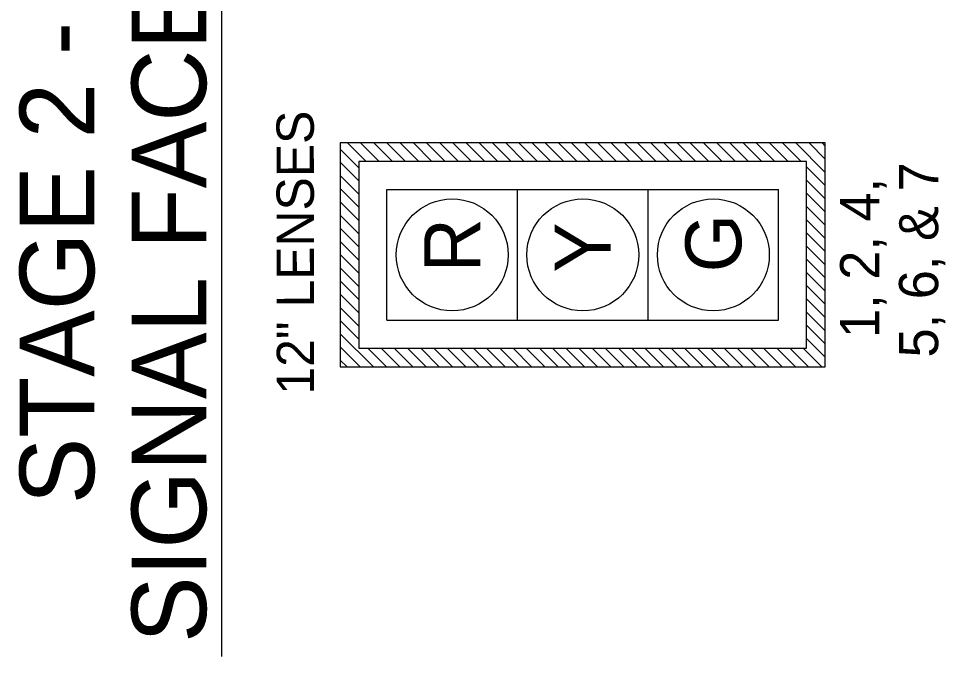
# Model space of a CAD drawing. Extents: x 610547 to 611161, y 419122 to 420064.
# Drawn here: x 610546.6 to 610646, y 419292 to 419360.3 of the extents above; entities that cross this region are included whole.
import ezdxf

# ---------------------------------------------------------------- set-up
doc = ezdxf.new("R2010")
doc.units = 0
for name, color, linetype in [('C-ANNO-TEXT', 7, 'Continuous'), ('Level 57', 7, 'Continuous'), ('Level 61', 7, 'Continuous'), ('T_Drafting', 7, 'Continuous')]:
    doc.layers.add(name, color=color, linetype=linetype)

msp = doc.modelspace()

# ---------------------------------------------------------------- linework, layer by layer
at = {"layer": 'Level 57'}
msp.add_line((610568.436, 419291.951), (610568.436, 419376.152), dxfattribs=at)
at = {"layer": 'T_Drafting'}
for p, q in [((610633.13, 419347.005), (610581.13, 419347.005)), ((610581.13, 419347.005), (610581.13, 419323.005)), ((610583.13, 419344.35), (610581.13, 419346.35)), ((610583.89, 419345.005), (610581.89, 419347.005)), ((610585.305, 419345.005), (610583.305, 419347.005)), ((610586.719, 419345.005), (610584.719, 419347.005)), ((610588.133, 419345.005), (610586.133, 419347.005)), ((610589.547, 419345.005), (610587.547, 419347.005)), ((610590.961, 419345.005), (610588.961, 419347.005)), ((610592.376, 419345.005), (610590.376, 419347.005)), ((610593.79, 419345.005), (610591.79, 419347.005)), ((610595.204, 419345.005), (610593.204, 419347.005)), ((610596.618, 419345.005), (610594.618, 419347.005)), ((610598.032, 419345.005), (610596.032, 419347.005)), ((610599.447, 419345.005), (610597.447, 419347.005)), ((610600.861, 419345.005), (610598.861, 419347.005)), ((610602.275, 419345.005), (610600.275, 419347.005)), ((610603.689, 419345.005), (610601.689, 419347.005)), ((610605.104, 419345.005), (610603.104, 419347.005)), ((610606.518, 419345.005), (610604.518, 419347.005)), ((610607.932, 419345.005), (610605.932, 419347.005)), ((610609.346, 419345.005), (610607.346, 419347.005)), ((610610.76, 419345.005), (610608.76, 419347.005)), ((610612.175, 419345.005), (610610.175, 419347.005)), ((610613.589, 419345.005), (610611.589, 419347.005)), ((610615.003, 419345.005), (610613.003, 419347.005)), ((610616.417, 419345.005), (610614.417, 419347.005)), ((610617.831, 419345.005), (610615.831, 419347.005)), ((610619.246, 419345.005), (610617.246, 419347.005)), ((610620.66, 419345.005), (610618.66, 419347.005)), ((610622.074, 419345.005), (610620.074, 419347.005)), ((610623.488, 419345.005), (610621.488, 419347.005)), ((610624.903, 419345.005), (610622.903, 419347.005)), ((610626.317, 419345.005), (610624.317, 419347.005)), ((610627.731, 419345.005), (610625.731, 419347.005)), ((610629.145, 419345.005), (610627.145, 419347.005)), ((610630.559, 419345.005), (610628.559, 419347.005)), ((610633.13, 419343.848), (610629.974, 419347.005)), ((610633.13, 419345.262), (610631.388, 419347.005)), ((610633.13, 419346.676), (610632.802, 419347.005)), ((610633.13, 419323.005), (610633.13, 419347.005)), ((610583.13, 419342.936), (610581.13, 419344.936)), ((610633.13, 419342.434), (610631.13, 419344.434)), ((610583.13, 419341.522), (610581.13, 419343.522)), ((610583.13, 419340.108), (610581.13, 419342.108)), ((610633.13, 419341.019), (610631.13, 419343.019)), ((610586.13, 419328.005), (610586.13, 419342.005)), ((610586.13, 419342.005), (610600.13, 419342.005)), ((610600.13, 419328.005), (610600.13, 419342.005)), ((610600.13, 419342.005), (610614.13, 419342.005)), ((610614.13, 419328.005), (610614.13, 419342.005)), ((610614.13, 419342.005), (610628.13, 419342.005)), ((610628.13, 419328.005), (610628.13, 419342.005)), ((610633.13, 419339.605), (610631.13, 419341.605)), ((610583.13, 419338.694), (610581.13, 419340.694)), ((610633.13, 419338.191), (610631.13, 419340.191)), ((610583.13, 419337.279), (610581.13, 419339.279)), ((610633.13, 419336.777), (610631.13, 419338.777)), ((610583.13, 419335.865), (610581.13, 419337.865)), ((610633.13, 419335.363), (610631.13, 419337.363)), ((610583.13, 419334.451), (610581.13, 419336.451)), ((610633.13, 419333.948), (610631.13, 419335.948)), ((610583.13, 419333.037), (610581.13, 419335.037)), ((610633.13, 419332.534), (610631.13, 419334.534)), ((610583.13, 419331.622), (610581.13, 419333.622)), ((610633.13, 419331.12), (610631.13, 419333.12)), ((610583.13, 419330.208), (610581.13, 419332.208)), ((610633.13, 419329.706), (610631.13, 419331.706)), ((610583.13, 419328.794), (610581.13, 419330.794)), ((610633.13, 419328.291), (610631.13, 419330.291)), ((610583.13, 419327.38), (610581.13, 419329.38)), ((610633.13, 419326.877), (610631.13, 419328.877)), ((610583.13, 419325.966), (610581.13, 419327.966)), ((610586.13, 419328.005), (610600.13, 419328.005)), ((610600.13, 419328.005), (610614.13, 419328.005)), ((610614.13, 419328.005), (610628.13, 419328.005)), ((610633.13, 419325.463), (610631.13, 419327.463)), ((610584.677, 419323.005), (610581.13, 419326.551)), ((610633.13, 419324.049), (610631.13, 419326.049)), ((610583.263, 419323.005), (610581.13, 419325.137)), ((610586.091, 419323.005), (610584.091, 419325.005)), ((610587.506, 419323.005), (610585.506, 419325.005)), ((610588.92, 419323.005), (610586.92, 419325.005)), ((610590.334, 419323.005), (610588.334, 419325.005)), ((610591.748, 419323.005), (610589.748, 419325.005)), ((610593.162, 419323.005), (610591.162, 419325.005)), ((610594.577, 419323.005), (610592.577, 419325.005)), ((610595.991, 419323.005), (610593.991, 419325.005)), ((610597.405, 419323.005), (610595.405, 419325.005)), ((610598.819, 419323.005), (610596.819, 419325.005)), ((610600.234, 419323.005), (610598.234, 419325.005)), ((610601.648, 419323.005), (610599.648, 419325.005)), ((610603.062, 419323.005), (610601.062, 419325.005)), ((610604.476, 419323.005), (610602.476, 419325.005)), ((610605.89, 419323.005), (610603.89, 419325.005)), ((610607.305, 419323.005), (610605.305, 419325.005)), ((610608.719, 419323.005), (610606.719, 419325.005)), ((610610.133, 419323.005), (610608.133, 419325.005)), ((610611.547, 419323.005), (610609.547, 419325.005)), ((610612.961, 419323.005), (610610.961, 419325.005)), ((610614.376, 419323.005), (610612.376, 419325.005)), ((610615.79, 419323.005), (610613.79, 419325.005)), ((610617.204, 419323.005), (610615.204, 419325.005)), ((610618.618, 419323.005), (610616.618, 419325.005)), ((610620.032, 419323.005), (610618.032, 419325.005)), ((610621.447, 419323.005), (610619.447, 419325.005)), ((610622.861, 419323.005), (610620.861, 419325.005)), ((610624.275, 419323.005), (610622.275, 419325.005)), ((610625.689, 419323.005), (610623.689, 419325.005)), ((610627.104, 419323.005), (610625.104, 419325.005)), ((610628.518, 419323.005), (610626.518, 419325.005)), ((610629.932, 419323.005), (610627.932, 419325.005)), ((610631.346, 419323.005), (610629.346, 419325.005)), ((610632.76, 419323.005), (610630.76, 419325.005)), ((610581.849, 419323.005), (610581.13, 419323.723)), ((610581.13, 419323.005), (610633.13, 419323.005))]:
    msp.add_line(p, q, dxfattribs=at)
msp.add_lwpolyline([(610631.13, 419345.005), (610583.13, 419345.005), (610583.13, 419325.005), (610631.13, 419325.005)], close=True, dxfattribs=at)
for centre in [(610593.13, 419335.005), (610607.13, 419335.005), (610621.13, 419335.005)]:
    msp.add_circle(centre, 6, dxfattribs=at)

# ---------------------------------------------------------------- texts
at = {"layer": 'C-ANNO-TEXT'}
for s, p in [('5, 6, & 7', (610645.237, 419324.005)), ('1, 2, 4, ', (610638.916, 419326.091))]:
    msp.add_text(s, height=4.2, rotation=90, dxfattribs=at).set_placement(p)
at = {"layer": 'Level 61'}
for s, height, rotation, p in [('SIGNAL FACES', 8, 90, (610566.747, 419293.401)), ('     STAGE 2 - ', 8, 90, (610554.747, 419293.401)), ('12" LENSES', 4, 90.07203, (610578.323, 419320.025))]:
    msp.add_text(s, height=height, rotation=rotation, dxfattribs=at).set_placement(p)
at = {"layer": 'T_Drafting'}
for s, p in [('R', (610596.129, 419333.139)), ('Y', (610610.129, 419333.116)), ('G', (610624.129, 419333.138))]:
    msp.add_text(s, height=5.998, rotation=90, dxfattribs=at).set_placement(p)

doc.saveas('drawing.dxf')
